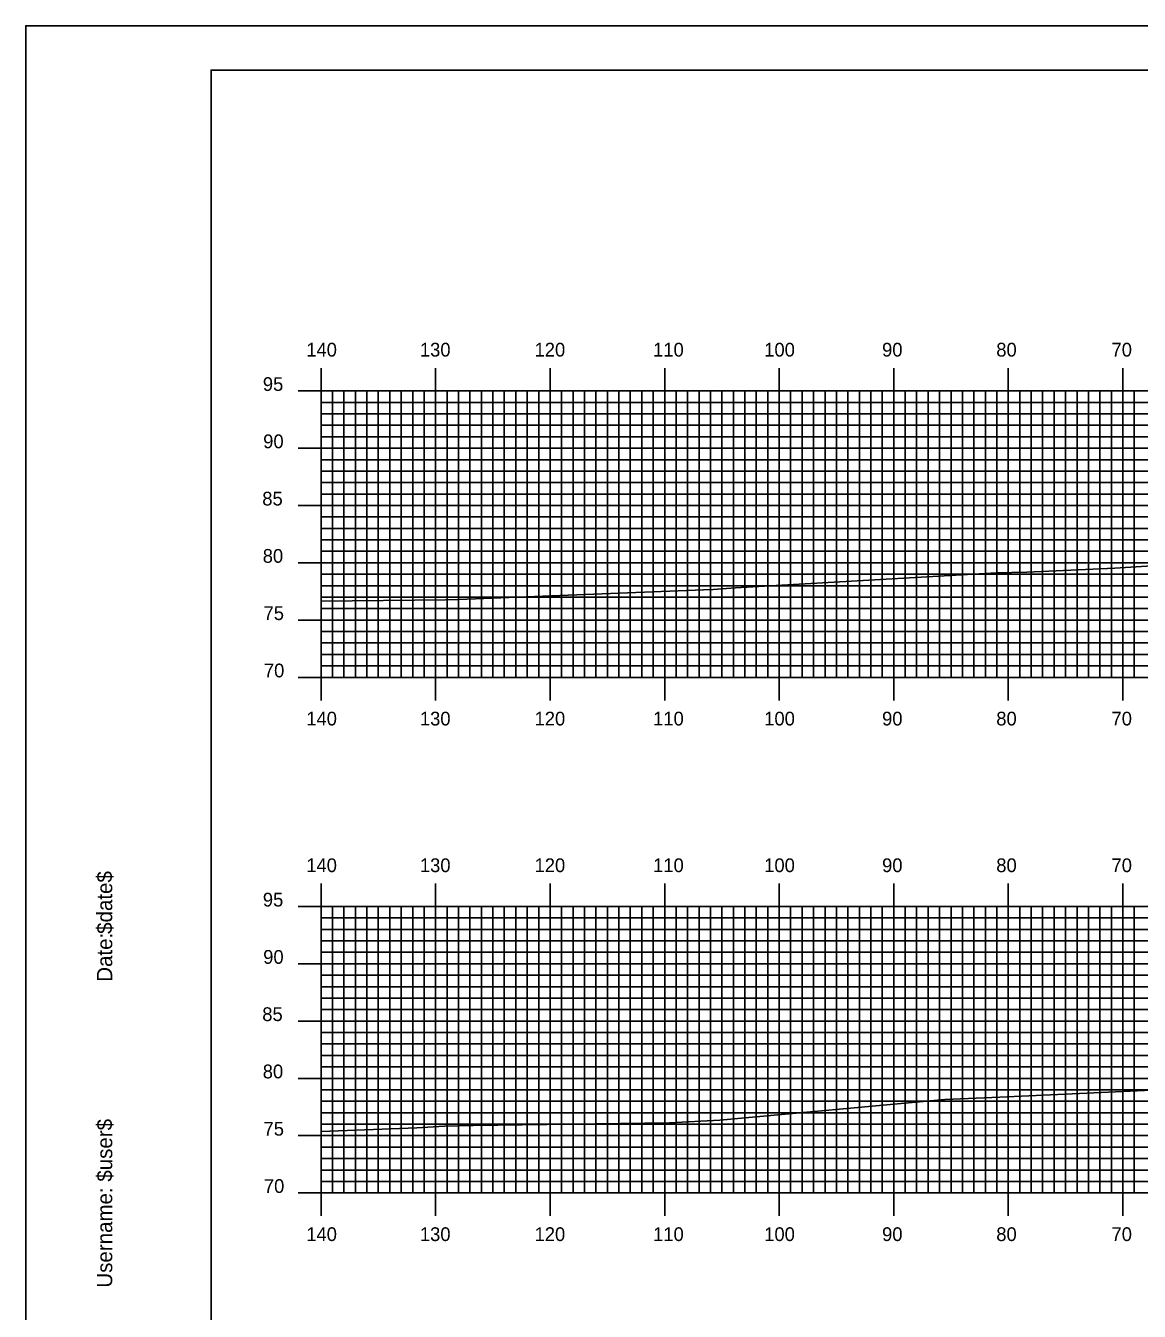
# Model space of a CAD drawing. Extents: x 1777138 to 1777481, y 442591 to 442811.
# Drawn here: x 1777138 to 1777235.2, y 442698.3 to 442810.5 of the extents above; entities that cross this region are included whole.
import ezdxf

# ---------------------------------------------------------------- set-up
doc = ezdxf.new("R2010")
doc.units = 0
for name, color, linetype in [('BORDER', 7, 'Continuous'), ('H_V ANNOTATION', 7, 'Continuous'), ('MAJOR', 7, 'Continuous'), ('MINOR', 7, 'Continuous'), ('PLOT BOUNDARY', 7, 'Continuous'), ('S_Roadway_Centerline', 7, 'Continuous')]:
    doc.layers.add(name, color=color, linetype=linetype)

msp = doc.modelspace()

# ---------------------------------------------------------------- linework, layer by layer
at = {"layer": 'BORDER'}
msp.add_lwpolyline([(1777154.16, 442596.67), (1777474.16, 442596.67), (1777474.16, 442806.67), (1777154.16, 442806.67)], close=True, dxfattribs=at)
at = {"layer": 'MAJOR'}
for p, q in [((1777163.76, 442780.67), (1777163.76, 442778.67)), ((1777173.76, 442780.67), (1777173.76, 442778.67)), ((1777183.76, 442780.67), (1777183.76, 442778.67)), ((1777193.76, 442780.67), (1777193.76, 442778.67)), ((1777203.76, 442780.67), (1777203.76, 442778.67)), ((1777213.76, 442780.67), (1777213.76, 442778.67)), ((1777223.76, 442780.67), (1777223.76, 442778.67)), ((1777233.76, 442780.67), (1777233.76, 442778.67)), ((1777161.76, 442778.67), (1777163.76, 442778.67)), ((1777163.76, 442778.67), (1777443.76, 442778.67)), ((1777163.76, 442753.67), (1777163.76, 442778.67)), ((1777163.76, 442753.67), (1777163.76, 442778.67)), ((1777163.76, 442778.67), (1777443.76, 442778.67)), ((1777173.76, 442753.67), (1777173.76, 442778.67)), ((1777183.76, 442753.67), (1777183.76, 442778.67)), ((1777193.76, 442753.67), (1777193.76, 442778.67)), ((1777203.76, 442753.67), (1777203.76, 442778.67)), ((1777213.76, 442753.67), (1777213.76, 442778.67)), ((1777223.76, 442753.67), (1777223.76, 442778.67)), ((1777233.76, 442753.67), (1777233.76, 442778.67)), ((1777161.76, 442773.67), (1777163.76, 442773.67)), ((1777163.76, 442773.67), (1777443.76, 442773.67)), ((1777161.76, 442768.67), (1777163.76, 442768.67)), ((1777163.76, 442768.67), (1777443.76, 442768.67)), ((1777161.76, 442763.67), (1777163.76, 442763.67)), ((1777163.76, 442763.67), (1777443.76, 442763.67)), ((1777161.76, 442758.67), (1777163.76, 442758.67)), ((1777163.76, 442758.67), (1777443.76, 442758.67)), ((1777161.76, 442753.67), (1777163.76, 442753.67)), ((1777163.76, 442753.67), (1777443.76, 442753.67)), ((1777163.76, 442753.67), (1777443.76, 442753.67)), ((1777163.76, 442751.66), (1777163.76, 442753.67)), ((1777173.76, 442751.66), (1777173.76, 442753.67)), ((1777183.76, 442751.66), (1777183.76, 442753.67)), ((1777193.76, 442751.66), (1777193.76, 442753.67)), ((1777203.76, 442751.66), (1777203.76, 442753.67)), ((1777213.76, 442751.66), (1777213.76, 442753.67)), ((1777223.76, 442751.66), (1777223.76, 442753.67)), ((1777233.76, 442751.66), (1777233.76, 442753.67)), ((1777163.76, 442735.67), (1777163.76, 442733.67)), ((1777173.76, 442735.67), (1777173.76, 442733.67)), ((1777183.76, 442735.67), (1777183.76, 442733.67)), ((1777193.76, 442735.67), (1777193.76, 442733.67)), ((1777203.76, 442735.67), (1777203.76, 442733.67)), ((1777213.76, 442735.67), (1777213.76, 442733.67)), ((1777223.76, 442735.67), (1777223.76, 442733.67)), ((1777233.76, 442735.67), (1777233.76, 442733.67)), ((1777161.76, 442733.67), (1777163.76, 442733.67)), ((1777163.76, 442733.67), (1777443.76, 442733.67)), ((1777163.76, 442708.67), (1777163.76, 442733.67)), ((1777163.76, 442708.67), (1777163.76, 442733.67)), ((1777163.76, 442733.67), (1777443.76, 442733.67)), ((1777173.76, 442708.67), (1777173.76, 442733.67)), ((1777183.76, 442708.67), (1777183.76, 442733.67)), ((1777193.76, 442708.67), (1777193.76, 442733.67)), ((1777203.76, 442708.67), (1777203.76, 442733.67)), ((1777213.76, 442708.67), (1777213.76, 442733.67)), ((1777223.76, 442708.67), (1777223.76, 442733.67)), ((1777233.76, 442708.67), (1777233.76, 442733.67)), ((1777161.76, 442728.67), (1777163.76, 442728.67)), ((1777163.76, 442728.67), (1777443.76, 442728.67)), ((1777161.76, 442723.67), (1777163.76, 442723.67)), ((1777163.76, 442723.67), (1777443.76, 442723.67)), ((1777161.76, 442718.67), (1777163.76, 442718.67)), ((1777163.76, 442718.67), (1777443.76, 442718.67)), ((1777161.76, 442713.67), (1777163.76, 442713.67)), ((1777163.76, 442713.67), (1777443.76, 442713.67)), ((1777161.76, 442708.67), (1777163.76, 442708.67)), ((1777163.76, 442708.67), (1777443.76, 442708.67)), ((1777163.76, 442708.67), (1777443.76, 442708.67)), ((1777163.76, 442706.66), (1777163.76, 442708.67)), ((1777173.76, 442706.66), (1777173.76, 442708.67)), ((1777183.76, 442706.66), (1777183.76, 442708.67)), ((1777193.76, 442706.66), (1777193.76, 442708.67)), ((1777203.76, 442706.66), (1777203.76, 442708.67)), ((1777213.76, 442706.66), (1777213.76, 442708.67)), ((1777223.76, 442706.66), (1777223.76, 442708.67)), ((1777233.76, 442706.66), (1777233.76, 442708.67))]:
    msp.add_line(p, q, dxfattribs=at)
at = {"layer": 'MINOR'}
for p, q in [((1777164.76, 442753.67), (1777164.76, 442778.67)), ((1777165.76, 442753.67), (1777165.76, 442778.67)), ((1777166.76, 442753.67), (1777166.76, 442778.67)), ((1777167.76, 442753.67), (1777167.76, 442778.67)), ((1777168.76, 442753.67), (1777168.76, 442778.67)), ((1777169.76, 442753.67), (1777169.76, 442778.67)), ((1777170.76, 442753.67), (1777170.76, 442778.67)), ((1777171.76, 442753.67), (1777171.76, 442778.67)), ((1777172.76, 442753.67), (1777172.76, 442778.67)), ((1777174.76, 442753.67), (1777174.76, 442778.67)), ((1777175.76, 442753.67), (1777175.76, 442778.67)), ((1777176.76, 442753.67), (1777176.76, 442778.67)), ((1777177.76, 442753.67), (1777177.76, 442778.67)), ((1777178.76, 442753.67), (1777178.76, 442778.67)), ((1777179.76, 442753.67), (1777179.76, 442778.67)), ((1777180.76, 442753.67), (1777180.76, 442778.67)), ((1777181.76, 442753.67), (1777181.76, 442778.67)), ((1777182.76, 442753.67), (1777182.76, 442778.67)), ((1777184.76, 442753.67), (1777184.76, 442778.67)), ((1777185.76, 442753.67), (1777185.76, 442778.67)), ((1777186.76, 442753.67), (1777186.76, 442778.67)), ((1777187.76, 442753.67), (1777187.76, 442778.67)), ((1777188.76, 442753.67), (1777188.76, 442778.67)), ((1777189.76, 442753.67), (1777189.76, 442778.67)), ((1777190.76, 442753.67), (1777190.76, 442778.67)), ((1777191.76, 442753.67), (1777191.76, 442778.67)), ((1777192.76, 442753.67), (1777192.76, 442778.67)), ((1777194.76, 442753.67), (1777194.76, 442778.67)), ((1777195.76, 442753.67), (1777195.76, 442778.67)), ((1777196.76, 442753.67), (1777196.76, 442778.67)), ((1777197.76, 442753.67), (1777197.76, 442778.67)), ((1777198.76, 442753.67), (1777198.76, 442778.67)), ((1777199.76, 442753.67), (1777199.76, 442778.67)), ((1777200.76, 442753.67), (1777200.76, 442778.67)), ((1777201.76, 442753.67), (1777201.76, 442778.67)), ((1777202.76, 442753.67), (1777202.76, 442778.67)), ((1777204.76, 442753.67), (1777204.76, 442778.67)), ((1777205.76, 442753.67), (1777205.76, 442778.67)), ((1777206.76, 442753.67), (1777206.76, 442778.67)), ((1777207.76, 442753.67), (1777207.76, 442778.67)), ((1777208.76, 442753.67), (1777208.76, 442778.67)), ((1777209.76, 442753.67), (1777209.76, 442778.67)), ((1777210.76, 442753.67), (1777210.76, 442778.67)), ((1777211.76, 442753.67), (1777211.76, 442778.67)), ((1777212.76, 442753.67), (1777212.76, 442778.67)), ((1777214.76, 442753.67), (1777214.76, 442778.67)), ((1777215.76, 442753.67), (1777215.76, 442778.67)), ((1777216.76, 442753.67), (1777216.76, 442778.67)), ((1777217.76, 442753.67), (1777217.76, 442778.67)), ((1777218.76, 442753.67), (1777218.76, 442778.67)), ((1777219.76, 442753.67), (1777219.76, 442778.67)), ((1777220.76, 442753.67), (1777220.76, 442778.67)), ((1777221.76, 442753.67), (1777221.76, 442778.67)), ((1777222.76, 442753.67), (1777222.76, 442778.67)), ((1777224.76, 442753.67), (1777224.76, 442778.67)), ((1777225.76, 442753.67), (1777225.76, 442778.67)), ((1777226.76, 442753.67), (1777226.76, 442778.67)), ((1777227.76, 442753.67), (1777227.76, 442778.67)), ((1777228.76, 442753.67), (1777228.76, 442778.67)), ((1777229.76, 442753.67), (1777229.76, 442778.67)), ((1777230.76, 442753.67), (1777230.76, 442778.67)), ((1777231.76, 442753.67), (1777231.76, 442778.67)), ((1777232.76, 442753.67), (1777232.76, 442778.67)), ((1777234.76, 442753.67), (1777234.76, 442778.67)), ((1777163.76, 442777.67), (1777443.76, 442777.67)), ((1777163.76, 442777.67), (1777165.77, 442777.67)), ((1777163.76, 442776.67), (1777443.76, 442776.67)), ((1777163.76, 442776.67), (1777165.77, 442776.67)), ((1777163.76, 442775.67), (1777443.76, 442775.67)), ((1777163.76, 442775.67), (1777165.77, 442775.67)), ((1777163.76, 442774.67), (1777443.76, 442774.67)), ((1777163.76, 442774.67), (1777165.77, 442774.67)), ((1777163.76, 442772.67), (1777443.76, 442772.67)), ((1777163.76, 442772.67), (1777165.77, 442772.67)), ((1777163.76, 442771.67), (1777443.76, 442771.67)), ((1777163.76, 442771.67), (1777165.77, 442771.67)), ((1777163.76, 442770.67), (1777443.76, 442770.67)), ((1777163.76, 442770.67), (1777165.77, 442770.67)), ((1777163.76, 442769.67), (1777443.76, 442769.67)), ((1777163.76, 442769.67), (1777165.77, 442769.67)), ((1777163.76, 442767.67), (1777443.76, 442767.67)), ((1777163.76, 442767.67), (1777165.77, 442767.67)), ((1777163.76, 442766.67), (1777443.76, 442766.67)), ((1777163.76, 442766.67), (1777165.77, 442766.67)), ((1777163.76, 442765.67), (1777443.76, 442765.67)), ((1777163.76, 442765.67), (1777165.77, 442765.67)), ((1777163.76, 442764.67), (1777443.76, 442764.67)), ((1777163.76, 442764.67), (1777165.77, 442764.67)), ((1777163.76, 442762.67), (1777443.76, 442762.67)), ((1777163.76, 442762.67), (1777165.77, 442762.67)), ((1777163.76, 442761.67), (1777443.76, 442761.67)), ((1777163.76, 442761.67), (1777165.77, 442761.67)), ((1777163.76, 442760.67), (1777443.76, 442760.67)), ((1777163.76, 442760.67), (1777165.77, 442760.67)), ((1777163.76, 442759.67), (1777443.76, 442759.67)), ((1777163.76, 442759.67), (1777165.77, 442759.67)), ((1777163.76, 442757.67), (1777443.76, 442757.67)), ((1777163.76, 442757.67), (1777165.77, 442757.67)), ((1777163.76, 442756.67), (1777443.76, 442756.67)), ((1777163.76, 442756.67), (1777165.77, 442756.67)), ((1777163.76, 442755.67), (1777443.76, 442755.67)), ((1777163.76, 442755.67), (1777165.77, 442755.67)), ((1777163.76, 442754.67), (1777443.76, 442754.67)), ((1777163.76, 442754.67), (1777165.77, 442754.67)), ((1777164.76, 442708.67), (1777164.76, 442733.67)), ((1777165.76, 442708.67), (1777165.76, 442733.67)), ((1777166.76, 442708.67), (1777166.76, 442733.67)), ((1777167.76, 442708.67), (1777167.76, 442733.67)), ((1777168.76, 442708.67), (1777168.76, 442733.67)), ((1777169.76, 442708.67), (1777169.76, 442733.67)), ((1777170.76, 442708.67), (1777170.76, 442733.67)), ((1777171.76, 442708.67), (1777171.76, 442733.67)), ((1777172.76, 442708.67), (1777172.76, 442733.67)), ((1777174.76, 442708.67), (1777174.76, 442733.67)), ((1777175.76, 442708.67), (1777175.76, 442733.67)), ((1777176.76, 442708.67), (1777176.76, 442733.67)), ((1777177.76, 442708.67), (1777177.76, 442733.67)), ((1777178.76, 442708.67), (1777178.76, 442733.67)), ((1777179.76, 442708.67), (1777179.76, 442733.67)), ((1777180.76, 442708.67), (1777180.76, 442733.67)), ((1777181.76, 442708.67), (1777181.76, 442733.67)), ((1777182.76, 442708.67), (1777182.76, 442733.67)), ((1777184.76, 442708.67), (1777184.76, 442733.67)), ((1777185.76, 442708.67), (1777185.76, 442733.67)), ((1777186.76, 442708.67), (1777186.76, 442733.67)), ((1777187.76, 442708.67), (1777187.76, 442733.67)), ((1777188.76, 442708.67), (1777188.76, 442733.67)), ((1777189.76, 442708.67), (1777189.76, 442733.67)), ((1777190.76, 442708.67), (1777190.76, 442733.67)), ((1777191.76, 442708.67), (1777191.76, 442733.67)), ((1777192.76, 442708.67), (1777192.76, 442733.67)), ((1777194.76, 442708.67), (1777194.76, 442733.67)), ((1777195.76, 442708.67), (1777195.76, 442733.67)), ((1777196.76, 442708.67), (1777196.76, 442733.67)), ((1777197.76, 442708.67), (1777197.76, 442733.67)), ((1777198.76, 442708.67), (1777198.76, 442733.67)), ((1777199.76, 442708.67), (1777199.76, 442733.67)), ((1777200.76, 442708.67), (1777200.76, 442733.67)), ((1777201.76, 442708.67), (1777201.76, 442733.67)), ((1777202.76, 442708.67), (1777202.76, 442733.67)), ((1777204.76, 442708.67), (1777204.76, 442733.67)), ((1777205.76, 442708.67), (1777205.76, 442733.67)), ((1777206.76, 442708.67), (1777206.76, 442733.67)), ((1777207.76, 442708.67), (1777207.76, 442733.67)), ((1777208.76, 442708.67), (1777208.76, 442733.67)), ((1777209.76, 442708.67), (1777209.76, 442733.67)), ((1777210.76, 442708.67), (1777210.76, 442733.67)), ((1777211.76, 442708.67), (1777211.76, 442733.67)), ((1777212.76, 442708.67), (1777212.76, 442733.67)), ((1777214.76, 442708.67), (1777214.76, 442733.67)), ((1777215.76, 442708.67), (1777215.76, 442733.67)), ((1777216.76, 442708.67), (1777216.76, 442733.67)), ((1777217.76, 442708.67), (1777217.76, 442733.67)), ((1777218.76, 442708.67), (1777218.76, 442733.67)), ((1777219.76, 442708.67), (1777219.76, 442733.67)), ((1777220.76, 442708.67), (1777220.76, 442733.67)), ((1777221.76, 442708.67), (1777221.76, 442733.67)), ((1777222.76, 442708.67), (1777222.76, 442733.67)), ((1777224.76, 442708.67), (1777224.76, 442733.67)), ((1777225.76, 442708.67), (1777225.76, 442733.67)), ((1777226.76, 442708.67), (1777226.76, 442733.67)), ((1777227.76, 442708.67), (1777227.76, 442733.67)), ((1777228.76, 442708.67), (1777228.76, 442733.67)), ((1777229.76, 442708.67), (1777229.76, 442733.67)), ((1777230.76, 442708.67), (1777230.76, 442733.67)), ((1777231.76, 442708.67), (1777231.76, 442733.67)), ((1777232.76, 442708.67), (1777232.76, 442733.67)), ((1777234.76, 442708.67), (1777234.76, 442733.67)), ((1777163.76, 442732.67), (1777443.76, 442732.67)), ((1777163.76, 442732.67), (1777165.77, 442732.67)), ((1777163.76, 442731.67), (1777443.76, 442731.67)), ((1777163.76, 442731.67), (1777165.77, 442731.67)), ((1777163.76, 442730.67), (1777443.76, 442730.67)), ((1777163.76, 442730.67), (1777165.77, 442730.67)), ((1777163.76, 442729.67), (1777443.76, 442729.67)), ((1777163.76, 442729.67), (1777165.77, 442729.67)), ((1777163.76, 442727.67), (1777443.76, 442727.67)), ((1777163.76, 442727.67), (1777165.77, 442727.67)), ((1777163.76, 442726.67), (1777443.76, 442726.67)), ((1777163.76, 442726.67), (1777165.77, 442726.67)), ((1777163.76, 442725.67), (1777443.76, 442725.67)), ((1777163.76, 442725.67), (1777165.77, 442725.67)), ((1777163.76, 442724.67), (1777443.76, 442724.67)), ((1777163.76, 442724.67), (1777165.77, 442724.67)), ((1777163.76, 442722.67), (1777443.76, 442722.67)), ((1777163.76, 442722.67), (1777165.77, 442722.67)), ((1777163.76, 442721.67), (1777443.76, 442721.67)), ((1777163.76, 442721.67), (1777165.77, 442721.67)), ((1777163.76, 442720.67), (1777443.76, 442720.67)), ((1777163.76, 442720.67), (1777165.77, 442720.67)), ((1777163.76, 442719.67), (1777443.76, 442719.67)), ((1777163.76, 442719.67), (1777165.77, 442719.67)), ((1777163.76, 442717.67), (1777443.76, 442717.67)), ((1777163.76, 442717.67), (1777165.77, 442717.67)), ((1777163.76, 442716.67), (1777443.76, 442716.67)), ((1777163.76, 442716.67), (1777165.77, 442716.67)), ((1777163.76, 442715.67), (1777443.76, 442715.67)), ((1777163.76, 442715.67), (1777165.77, 442715.67)), ((1777163.76, 442714.67), (1777443.76, 442714.67)), ((1777163.76, 442714.67), (1777165.77, 442714.67)), ((1777163.76, 442712.67), (1777443.76, 442712.67)), ((1777163.76, 442712.67), (1777165.77, 442712.67)), ((1777163.76, 442711.67), (1777443.76, 442711.67)), ((1777163.76, 442711.67), (1777165.77, 442711.67)), ((1777163.76, 442710.67), (1777443.76, 442710.67)), ((1777163.76, 442710.67), (1777165.77, 442710.67)), ((1777163.76, 442709.67), (1777443.76, 442709.67)), ((1777163.76, 442709.67), (1777165.77, 442709.67))]:
    msp.add_line(p, q, dxfattribs=at)
at = {"layer": 'PLOT BOUNDARY'}
msp.add_lwpolyline([(1777137.98, 442590.55), (1777477.98, 442590.55), (1777477.98, 442810.55), (1777137.98, 442810.55)], close=True, dxfattribs=at)
at = {"layer": 'S_Roadway_Centerline'}
for points in [[(1777163.76, 442760.32), (1777174.64, 442760.43), (1777175.77, 442760.46), (1777197.15, 442761.32), (1777197.98, 442761.35), (1777199.94, 442761.47), (1777222.74, 442762.79), (1777225.37, 442762.84), (1777233.05, 442763.19), (1777242.81, 442763.82)], [(1777163.76, 442714.04), (1777172.11, 442714.36), (1777174.53, 442714.49), (1777177.04, 442714.56), (1777194.18, 442714.79), (1777198.59, 442715.01), (1777218.23, 442716.82), (1777223.02, 442717.02), (1777242.61, 442717.93)]]:
    msp.add_lwpolyline(points, dxfattribs=at)

# ---------------------------------------------------------------- texts
at = {"layer": 'BORDER'}
for s, p in [('$date$', (1777145.53, 442731.28)), ('Date:', (1777145.53, 442727.1)), ('$user$', (1777145.53, 442709.65)), ('Username:', (1777145.53, 442700.4))]:
    msp.add_text(s, height=1.339, rotation=90, dxfattribs=at).set_placement(p)
at = {"layer": 'H_V ANNOTATION'}
for s, p in [('140', (1777162.47, 442781.67)), ('130', (1777172.39, 442781.67)), ('120', (1777182.4, 442781.67)), ('110', (1777192.75, 442781.67)), ('100', (1777202.45, 442781.67)), ('90', (1777212.74, 442781.67)), ('80', (1777222.71, 442781.67)), ('70', (1777232.77, 442781.67)), ('95', (1777158.68, 442778.67)), ('90', (1777158.71, 442773.67)), ('85', (1777158.63, 442768.67)), ('80', (1777158.67, 442763.67)), ('75', (1777158.74, 442758.67)), ('70', (1777158.77, 442753.67)), ('140', (1777162.47, 442749.47)), ('130', (1777172.39, 442749.47)), ('120', (1777182.4, 442749.47)), ('110', (1777192.75, 442749.47)), ('100', (1777202.45, 442749.47)), ('90', (1777212.74, 442749.47)), ('80', (1777222.71, 442749.47)), ('70', (1777232.77, 442749.47)), ('140', (1777162.47, 442736.67)), ('130', (1777172.39, 442736.67)), ('120', (1777182.4, 442736.67)), ('110', (1777192.75, 442736.67)), ('100', (1777202.45, 442736.67)), ('90', (1777212.74, 442736.67)), ('80', (1777222.71, 442736.67)), ('70', (1777232.77, 442736.67)), ('95', (1777158.68, 442733.67)), ('90', (1777158.71, 442728.67)), ('85', (1777158.63, 442723.67)), ('80', (1777158.67, 442718.67)), ('75', (1777158.74, 442713.67)), ('70', (1777158.77, 442708.67)), ('140', (1777162.47, 442704.47)), ('130', (1777172.39, 442704.47)), ('120', (1777182.4, 442704.47)), ('110', (1777192.75, 442704.47)), ('100', (1777202.45, 442704.47)), ('90', (1777212.74, 442704.47)), ('80', (1777222.71, 442704.47)), ('70', (1777232.77, 442704.47))]:
    msp.add_text(s, height=1.2, dxfattribs=at).set_placement(p)
at = {"layer": 'MAJOR'}
for p in [(1777163.75, 442753.67), (1777163.75, 442708.67)]:
    msp.add_text('-', height=0.012, dxfattribs=at).set_placement(p)

doc.saveas('drawing.dxf')
